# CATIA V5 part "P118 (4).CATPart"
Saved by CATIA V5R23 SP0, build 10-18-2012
Part number: 05-LICP-T02-E-S13-P118 (4)
Definition: butee a aiguilles
Description: butee_a_aiguilles_ax_19_32_04
Bounding box of the stored display mesh (mm): x 0 to 0.8, y -15.598 to 15.598, z -15.598 to 15.598
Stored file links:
  C:\wamp\www\COURS\CONCEPTION GMP1\TITRE 02-SEMESTRE 2\03-TP7-PRESSE MECANIQUE\eleve\P118 (4).CATPart
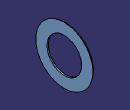
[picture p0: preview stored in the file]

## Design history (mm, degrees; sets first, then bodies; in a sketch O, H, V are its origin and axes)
Body1 (main body)
  Solid1: solid without history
